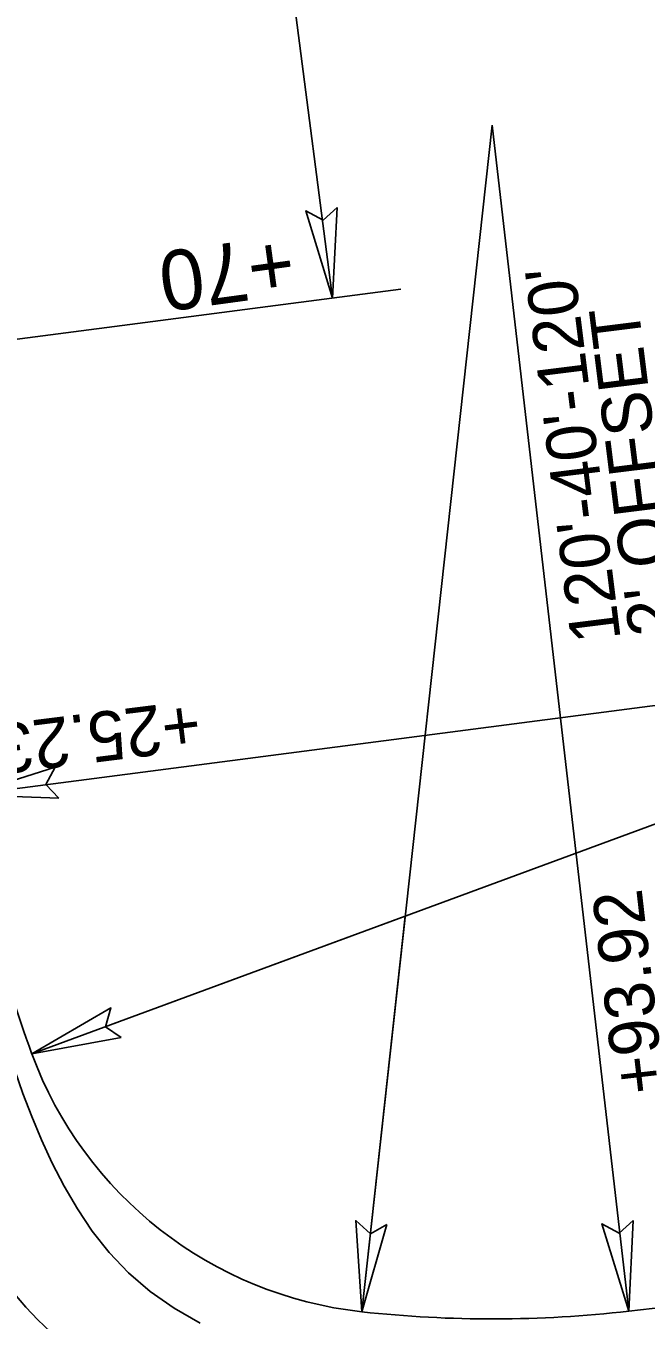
# Model space of a CAD drawing. Extents: x 2367848 to 2369479, y 800728 to 808616.
# Drawn here: x 2368395.5 to 2368457.9, y 807974.9 to 808105 of the extents above; entities that cross this region are included whole.
import ezdxf

# ---------------------------------------------------------------- set-up
doc = ezdxf.new("R2010")
doc.units = 0
for name, color, linetype in [('Prop AutoTurn Projected Path', 7, 'Continuous'), ('Prop AutoTurn Simulation', 7, 'Continuous'), ('Prop Dimension', 7, 'Continuous'), ('Prop Dimension Text', 7, 'Continuous'), ('Prop EOT', 7, 'Continuous'), ('Prop Terminator CELL', 7, 'Continuous'), ('Scratch_Level_1', 7, 'Continuous')]:
    doc.layers.add(name, color=color, linetype=linetype)

msp = doc.modelspace()

# ---------------------------------------------------------------- linework, layer by layer
at = {"layer": 'Prop AutoTurn Projected Path'}
for centre in [(2368421.62, 807999.55), (2368421.62, 807999.55), (2368411.59, 807983.71)]:
    msp.add_arc(centre, 35, 187.418, 279.3467, dxfattribs=at)
at = {"layer": 'Prop AutoTurn Simulation'}
msp.add_lwpolyline([(2368413.05, 807974.6), (2368410.43, 807976.09), (2368408.02, 807977.79), (2368405.84, 807979.66), (2368403.91, 807981.69), (2368402.21, 807983.85), (2368400.71, 807986.09), (2368399.38, 807988.38), (2368398.19, 807990.69), (2368397.11, 807993.02), (2368396.14, 807995.36), (2368395.24, 807997.69), (2368394.42, 808000.03), (2368393.67, 808002.36), (2368392.95, 808004.75), (2368392.44, 808006.53)], dxfattribs=at)
at = {"layer": 'Prop Dimension'}
for p, q in [((2368387.64, 808375.11), (2368426.37, 808077.62)), ((2368442.41, 808095.02), (2368429.3, 807975.74)), ((2368442.41, 808095.02), (2368456.13, 807975.81)), ((2368433.24, 808078.51), (2368384.99, 808072.23)), ((2368508.72, 808043.19), (2368389.72, 808027.7)), ((2368508.72, 808043.19), (2368396.14, 808001.65)), ((2368433.67, 808015.5), (2368396.14, 808001.65)), ((2368433.67, 808015.5), (2368429.3, 807975.74))]:
    msp.add_line(p, q, dxfattribs=at)
at = {"layer": 'Prop EOT'}
msp.add_line((2368456.13, 807975.81), (2368467.15, 807977.07), dxfattribs=at)
for centre, radius, start, end in [((2368508.72, 808043.19), 120, 187.418, 200.2566), ((2368433.67, 808015.5), 40, 200.2566, 263.7283), ((2368442.41, 808095.02), 120, 263.7283, 276.5669)]:
    msp.add_arc(centre, radius, start, end, dxfattribs=at)
at = {"layer": 'Prop Terminator CELL'}
for points in [[(2368426.82, 808086.74), (2368426.37, 808077.62), (2368423.69, 808086.41), (2368425.42, 808085.46)], [(2368398.85, 808027.35), (2368389.72, 808027.7), (2368398.48, 808030.48), (2368397.56, 808028.74)], [(2368405.12, 808003.31), (2368396.14, 808001.65), (2368404.08, 808006.28), (2368403.55, 808004.38)], [(2368431.82, 807984.51), (2368429.3, 807975.74), (2368428.7, 807984.91), (2368430.16, 807983.59)], [(2368456.57, 807984.93), (2368456.13, 807975.81), (2368453.44, 807984.59), (2368455.17, 807983.65)]]:
    msp.add_lwpolyline(points, close=True, dxfattribs=at)
at = {"layer": 'Scratch_Level_1'}
msp.add_arc((2368400.02, 807980.91), 35, 187.418, 279.304, dxfattribs=at)

# ---------------------------------------------------------------- texts
at = {"layer": 'Prop Dimension'}
msp.add_text('+70', height=6, rotation=187.7641, dxfattribs=at).set_placement((2368422.09, 808084.02))
at = {"layer": 'Prop Dimension Text'}
for s, rotation, p in [("120'-40'-120'", 97.1063, (2368455.34, 808043.31)), ("2' OFFSET", 97.1063, (2368461.19, 808044.04)), ('+25.23', 187.1063, (2368412.76, 808037.26)), ('+93.92', 96.5669, (2368459.77, 807997.89))]:
    msp.add_text(s, height=5, rotation=rotation, dxfattribs=at).set_placement(p)

doc.saveas('drawing.dxf')
